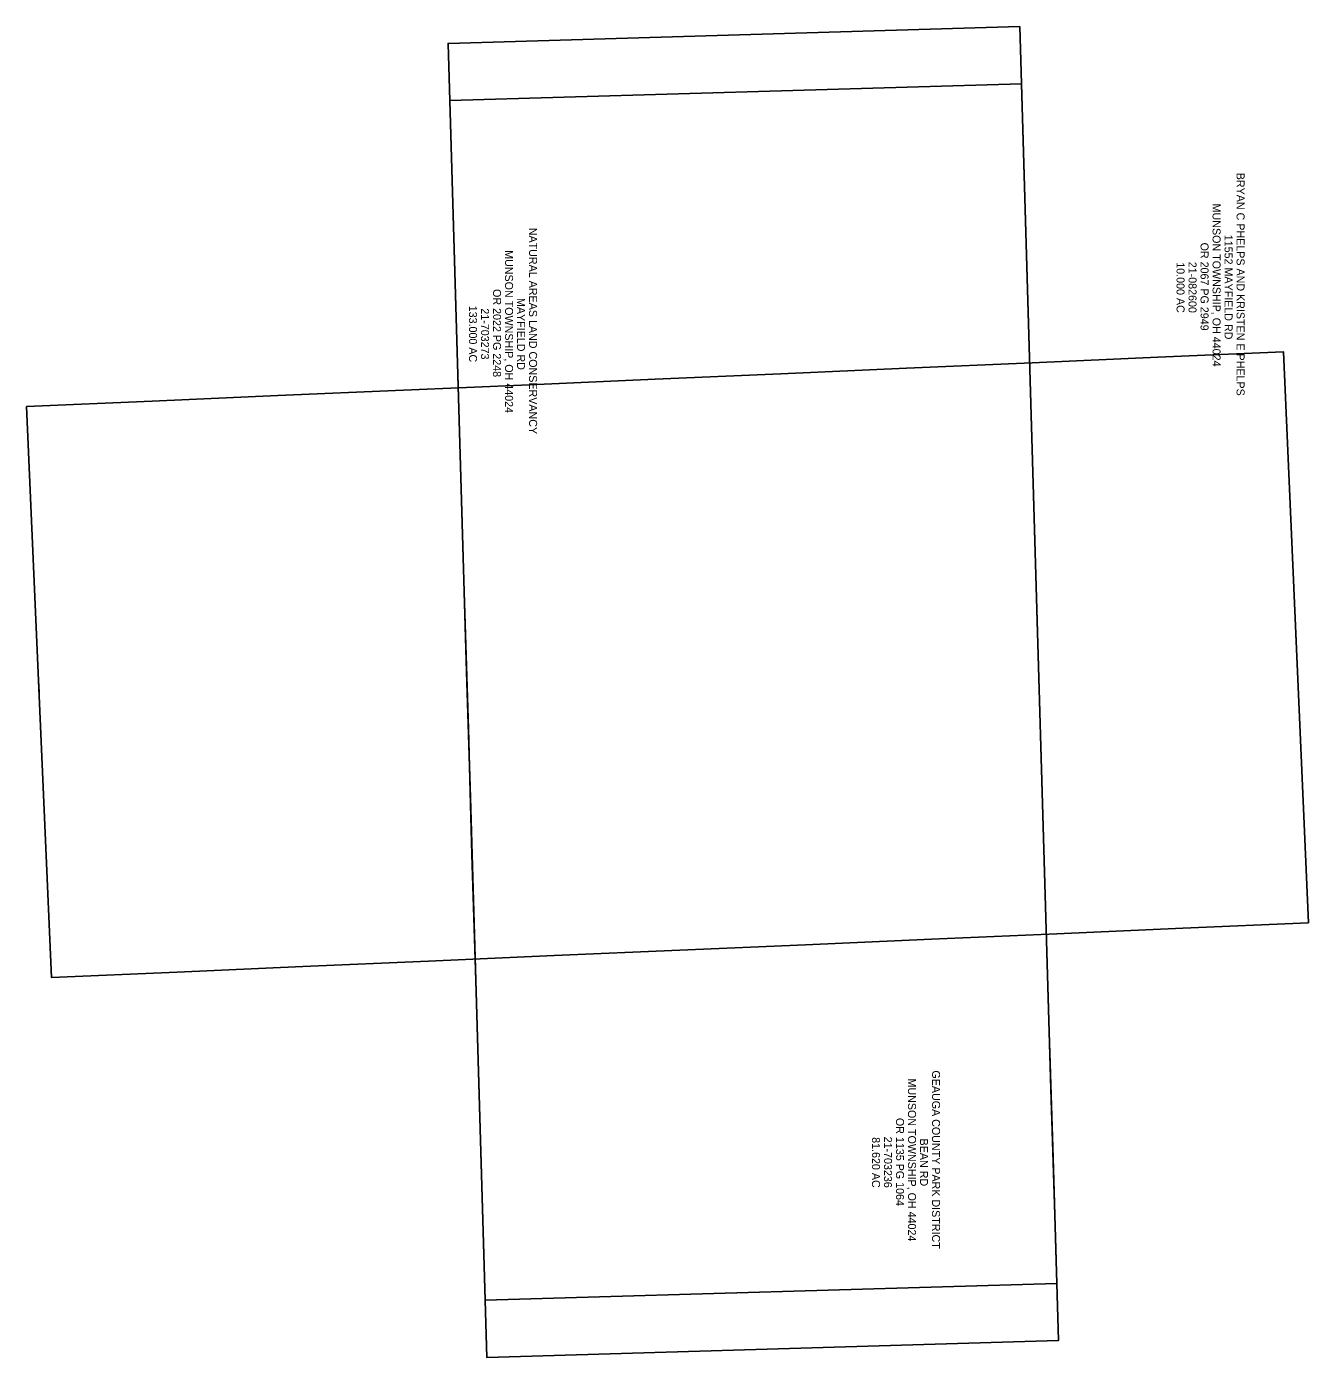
# Model space of a CAD drawing. Extents: x 2316849 to 2317073, y 680966 to 681199.
import ezdxf

# ---------------------------------------------------------------- set-up
doc = ezdxf.new("R2010")
doc.units = 0
for name, color, linetype in [('Default', 7, 'Continuous'), ('SN_X_Public', 7, 'Continuous'), ('SV_P_Mon_Cells_Set', 7, 'Continuous')]:
    doc.layers.add(name, color=color, linetype=linetype)

msp = doc.modelspace()

# ---------------------------------------------------------------- linework, layer by layer
at = {"layer": 'Default'}
for p, q in [((2317071.06, 681092.77), (2317071.14, 681090.77)), ((2316851.22, 681084.3), (2316851.3, 681082.3))]:
    msp.add_line(p, q, dxfattribs=at)
at = {"layer": 'SV_P_Mon_Cells_Set'}
for points in [[(2317022.8, 681198.73), (2316922.84, 681195.79), (2316923.49, 681173.8), (2316924.14, 681151.81), (2316924.78, 681129.82), (2316925.43, 681107.83), (2316926.07, 681085.84), (2316926.72, 681063.85), (2316927.37, 681041.86), (2316928.01, 681019.87), (2316928.66, 680997.88), (2316929.31, 680975.89), (2317029.26, 680978.82), (2317028.62, 681000.82), (2317027.97, 681022.81), (2317027.32, 681044.8), (2317026.68, 681066.79), (2317026.03, 681088.78), (2317025.38, 681110.77), (2317024.74, 681132.76), (2317024.09, 681154.75), (2317023.45, 681176.74)], [(2317023.09, 681188.73), (2316923.14, 681185.8), (2316923.78, 681163.81), (2316924.43, 681141.82), (2316925.08, 681119.82), (2316925.72, 681097.83), (2316926.37, 681075.84), (2316927.01, 681053.85), (2316927.66, 681031.86), (2316928.31, 681009.87), (2316928.95, 680987.88), (2316929.6, 680965.89), (2317029.56, 680968.83), (2317028.91, 680990.82), (2317028.26, 681012.81), (2317027.62, 681034.8), (2317026.97, 681056.79), (2317026.33, 681078.78), (2317025.68, 681100.77), (2317025.03, 681122.76), (2317024.39, 681144.75), (2317023.74, 681166.74)], [(2316849.13, 681132.25), (2316853.48, 681032.35), (2316875.46, 681033.3), (2316897.44, 681034.26), (2316919.42, 681035.22), (2316941.4, 681036.18), (2316963.38, 681037.14), (2316985.36, 681038.1), (2317007.34, 681039.06), (2317029.31, 681040.01), (2317051.29, 681040.97), (2317073.27, 681041.93), (2317068.92, 681141.84), (2317046.94, 681140.88), (2317024.96, 681139.92), (2317002.98, 681138.96), (2316981, 681138), (2316959.02, 681137.04), (2316937.04, 681136.08), (2316915.06, 681135.13), (2316893.08, 681134.17), (2316871.1, 681133.21)]]:
    msp.add_lwpolyline(points, close=True, dxfattribs=at)

# ---------------------------------------------------------------- texts
at = {"layer": 'SN_X_Public'}
for s, p in [('BRYAN C PHELPS AND KRISTEN E PHELPS', (2317060.72, 681173.16)), ('MUNSON TOWNSHIP, OH 44024', (2317056.52, 681167.76)), ('NATURAL AREAS LAND CONSERVANCY', (2316936.99, 681163.53)), ('OR 2067 PG 2949', (2317054.42, 681160.94)), ('11552 MAYFIELD RD', (2317058.62, 681162.31)), ('MUNSON TOWNSHIP, OH 44024', (2316932.79, 681159.62)), ('10.000 AC', (2317050.22, 681157.5)), ('21-082600', (2317052.32, 681157.59)), ('OR 2022 PG 2248', (2316930.69, 681152.81)), ('MAYFIELD RD', (2316934.89, 681151.25)), ('133.000 AC', (2316926.49, 681149.9)), ('21-703273', (2316928.59, 681149.44)), ('GEAUGA COUNTY PARK DISTRICT', (2317007.46, 681016.1)), ('MUNSON TOWNSHIP, OH 44024', (2317003.26, 681014.69)), ('OR 1135 PG 1064', (2317001.16, 681007.79)), ('81.620 AC', (2316996.96, 681004.42)), ('21-703236', (2316999.06, 681004.52)), ('BEAN RD', (2317005.36, 681004.17))]:
    msp.add_text(s, height=1.4, rotation=270, dxfattribs=at).set_placement(p)

doc.saveas('drawing.dxf')
